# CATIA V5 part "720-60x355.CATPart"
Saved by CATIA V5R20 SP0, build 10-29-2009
Part number: 720-60x355
Definition: NONE
Nomenclature: 720-60x355
Source: Unknown
Description: 720-60x355
Bounding box of the stored display mesh (mm): x 0 to 355, y -30 to 30, z -30 to 30
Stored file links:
  C:\Users\Utente\Desktop\IO LAVORO\3D X SITO CF\X SITO\720\720-60x355.CATPart
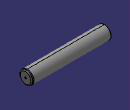
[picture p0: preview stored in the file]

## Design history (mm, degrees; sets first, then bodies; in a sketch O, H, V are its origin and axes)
Body1 "720-60x355" (main body)
  Solid1: solid without history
